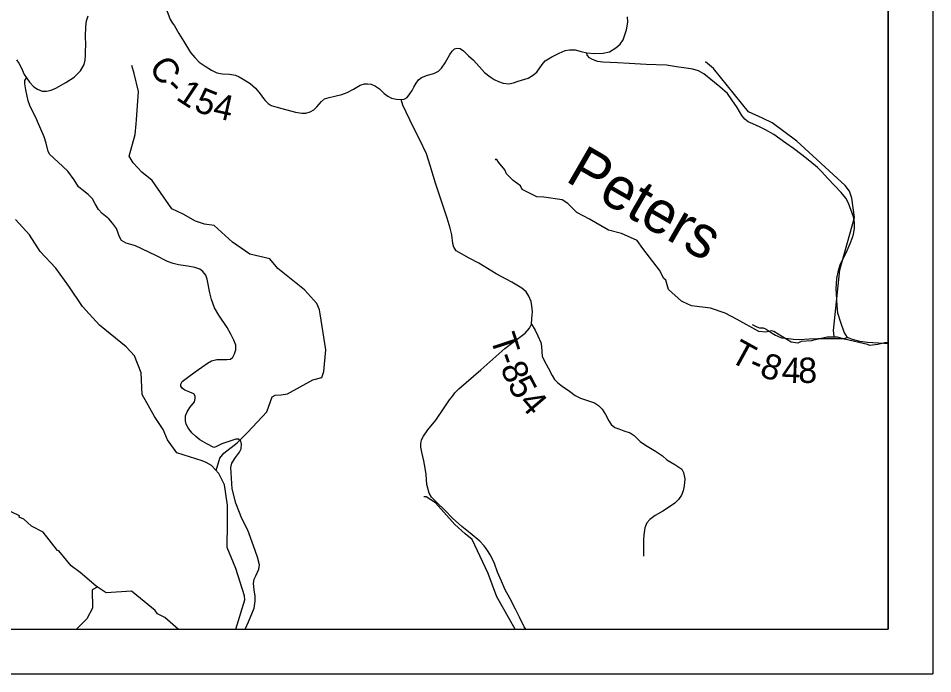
# Model space of a CAD drawing. Extents: x -1.8 to 75.7, y -2 to 25.
# Drawn here: x 48.65 to 50.7, y 15.612 to 17.082 of the extents above; entities that cross this region are included whole.
import ezdxf

# ---------------------------------------------------------------- set-up
doc = ezdxf.new("R2010")
doc.units = 0
for name, color, linetype in [('GM_X_County_Road', 7, 'Continuous'), ('GM_X_County_Road_Text', 7, 'Continuous'), ('GM_X_Minor_River', 7, 'Continuous'), ('GM_X_Minor_River_Text', 7, 'Continuous'), ('GM_X_Township', 7, 'Continuous'), ('GM_X_Township_Road', 7, 'Continuous'), ('GM_X_Township_Road_Text', 7, 'Continuous'), ('SH_Data', 7, 'Continuous')]:
    doc.layers.add(name, color=color, linetype=linetype)

msp = doc.modelspace()

# ---------------------------------------------------------------- linework, layer by layer
at = {"layer": 'GM_X_County_Road'}
for points in [[(48.9834, 17.0995), (48.9906, 17.0793), (48.9956, 17.0713), (49.0001, 17.0657), (49.0103, 17.0484), (49.0213, 17.0302), (49.0361, 17.0057), (49.0458, 16.9942), (49.0558, 16.9842), (49.0692, 16.9747), (49.0833, 16.9656), (49.0952, 16.9599), (49.1076, 16.9576), (49.1234, 16.9569), (49.1371, 16.9547), (49.1455, 16.9508), (49.1545, 16.9456), (49.17, 16.9357), (49.1815, 16.9259), (49.1921, 16.9129), (49.1997, 16.9025), (49.2036, 16.8976), (49.2105, 16.8915), (49.2172, 16.8869), (49.2276, 16.8835), (49.2406, 16.88), (49.2718, 16.8718), (49.2859, 16.8696), (49.2944, 16.8698), (49.3045, 16.8724), (49.3126, 16.8767), (49.3195, 16.8835), (49.3297, 16.8956), (49.3364, 16.9017), (49.3472, 16.9049), (49.3594, 16.9073), (49.3756, 16.9116), (49.3877, 16.9162), (49.4012, 16.9235), (49.4164, 16.932), (49.4259, 16.935), (49.4333, 16.9352), (49.4413, 16.9342), (49.4506, 16.93), (49.4595, 16.924), (49.4705, 16.9138), (49.4785, 16.9073), (49.487, 16.903), (49.498, 16.9006), (49.5083, 16.8999)], [(48.6458, 16.9892), (48.6515, 16.9814), (48.6569, 16.9706), (48.663, 16.9565), (48.6686, 16.9485), (48.6751, 16.9391), (48.6848, 16.9285), (48.6933, 16.9231), (48.7037, 16.9192), (48.7132, 16.919), (48.7234, 16.9212), (48.7338, 16.9259), (48.7563, 16.9381), (48.7756, 16.9504), (48.7893, 16.9647), (48.7974, 16.9788), (48.7997, 16.9885), (48.801, 16.9985), (48.8009, 17.0072), (48.8016, 17.0235), (48.8008, 17.0416), (48.8012, 17.0635), (48.8029, 17.077), (48.8064, 17.0878)], [(49.5083, 16.8999), (49.5155, 16.901), (49.5216, 16.9047), (49.528, 16.9131), (49.533, 16.9206), (49.5369, 16.9275), (49.5421, 16.9368), (49.5476, 16.9444), (49.5542, 16.9496), (49.5677, 16.9546), (49.5818, 16.9587), (49.5921, 16.9637), (49.5991, 16.9703), (49.6073, 16.9824), (49.6172, 17.0009), (49.6224, 17.0089), (49.6283, 17.0141), (49.634, 17.0155), (49.6406, 17.0148), (49.6484, 17.0093), (49.6593, 16.9982), (49.6703, 16.9884), (49.6764, 16.982), (49.684, 16.9733), (49.6954, 16.9608), (49.7077, 16.951), (49.7166, 16.9453), (49.7266, 16.9403), (49.7369, 16.9368), (49.7501, 16.9355), (49.7601, 16.9373), (49.7711, 16.9412), (49.793, 16.9481), (49.8032, 16.9541), (49.8123, 16.9612), (49.8242, 16.979), (49.8312, 16.987), (49.8461, 16.9957), (49.8625, 17.0041), (49.8764, 17.0098), (49.8862, 17.0114), (49.8983, 17.0116), (49.9122, 17.0082), (49.9247, 17.0051), (49.942, 17.0032), (49.9611, 17.0041), (49.9756, 17.0074), (49.9894, 17.0159), (49.9991, 17.024), (50.0061, 17.0341), (50.0135, 17.0561), (50.0164, 17.0734), (50.0155, 17.0857)]]:
    msp.add_lwpolyline(points, dxfattribs=at)
at = {"layer": 'GM_X_Minor_River'}
for points in [[(49.0935, 16.0677), (49.1021, 16.0953), (49.1107, 16.1072), (49.1409, 16.1297), (49.1647, 16.154), (49.2073, 16.1997), (49.2193, 16.2335), (49.2262, 16.2371), (49.2394, 16.2378), (49.2535, 16.24), (49.31, 16.2716), (49.3306, 16.2763), (49.3348, 16.2898), (49.3393, 16.3387), (49.3266, 16.4192), (49.325, 16.4284), (49.319, 16.4426), (49.2916, 16.4731), (49.2318, 16.5209), (49.2139, 16.5424), (49.1689, 16.5533), (49.13, 16.5804), (49.0892, 16.6178), (49.0673, 16.6204), (49.0471, 16.6271), (49.02, 16.6431), (48.9939, 16.6546), (48.9505, 16.7186), (48.9273, 16.7372), (48.9075, 16.7584), (48.8985, 16.7727), (48.9117, 16.8216), (48.9143, 16.8459), (48.9153, 16.8549), (48.9195, 16.9182), (48.9098, 16.9584), (48.9043, 16.9768)], [(50.4794, 16.3684), (50.4775, 16.3822), (50.4923, 16.5182), (50.5247, 16.6358), (50.5185, 16.6788), (50.5137, 16.6944), (50.5039, 16.707), (50.3957, 16.8066), (50.3402, 16.8476), (50.3182, 16.858), (50.2872, 16.8727), (50.2089, 16.9697), (50.1904, 16.9843)], [(50.6002, 16.3545), (50.593, 16.354), (50.5768, 16.3509), (50.559, 16.3486), (50.5541, 16.3509), (50.5023, 16.3625), (50.4868, 16.3671), (50.4634, 16.367), (50.4309, 16.3597), (50.4286, 16.3586), (50.4052, 16.357), (50.398, 16.3539), (50.3829, 16.3558), (50.3439, 16.38), (50.3386, 16.3815), (50.3258, 16.3781), (50.3106, 16.38), (50.2615, 16.4068), (50.235, 16.4208), (50.2017, 16.4322), (50.1594, 16.4374), (50.1397, 16.4465), (50.1367, 16.448), (50.1079, 16.4741), (50.1019, 16.4946), (50.0977, 16.4988), (50.0879, 16.517), (50.05, 16.566), (50.0379, 16.5842), (50.0027, 16.5997), (49.9729, 16.6072), (49.9305, 16.6314), (49.9025, 16.647), (49.8821, 16.6667), (49.8692, 16.675), (49.828, 16.681), (49.8129, 16.6821), (49.8008, 16.6878), (49.7962, 16.69), (49.78, 16.698), (49.7762, 16.7063), (49.7599, 16.7185), (49.7448, 16.7333), (49.741, 16.7424), (49.7266, 16.7598), (49.7228, 16.7659), (49.7202, 16.7651), (49.7213, 16.7678)], [(49.1376, 15.7121), (49.1578, 15.7776), (49.1573, 15.7867), (49.1377, 15.8481), (49.1183, 15.8954), (49.1188, 15.9501), (49.1189, 15.9903), (49.1124, 16.0361), (49.0995, 16.0612), (49.083, 16.0788), (49.0715, 16.0856), (49.0622, 16.0897), (49.0057, 16.1075), (48.9846, 16.137), (48.9751, 16.1601), (48.9552, 16.1888), (48.928, 16.2387), (48.9253, 16.287), (48.9102, 16.3254), (48.8915, 16.345), (48.8318, 16.394), (48.7941, 16.4362), (48.7634, 16.4812), (48.734, 16.5217), (48.6992, 16.5589), (48.675, 16.5965), (48.6436, 16.6309)], [(48.8468, 15.7937), (48.8248, 15.8084), (48.7884, 15.8395), (48.7684, 15.8543), (48.7408, 15.888), (48.7377, 15.8884), (48.7059, 15.9294), (48.6799, 15.943), (48.6621, 15.9589), (48.6519, 15.9634), (48.6526, 15.9661), (48.6182, 15.9824), (48.6008, 16.0017), (48.5944, 16.0028), (48.5713, 16.0347), (48.5539, 16.0487), (48.5417, 16.0418), (48.5506, 16.0468)], [(49.7637, 15.7121), (49.7227, 15.7842), (49.7035, 15.8368), (49.6673, 15.9132), (49.6522, 15.9262), (49.629, 15.9471), (49.5855, 15.9955), (49.5644, 16.0091), (49.5596, 16.009)], [(48.8285, 15.8067), (48.8153, 15.8003), (48.8163, 15.7589), (48.8039, 15.7354), (48.7803, 15.7121)], [(48.9036, 15.797), (48.8468, 15.7937)], [(49.0087, 15.7121), (48.9783, 15.7381), (48.9624, 15.7464), (48.9567, 15.754), (48.9079, 15.7945), (48.9036, 15.797)]]:
    msp.add_lwpolyline(points, dxfattribs=at)
at = {"layer": 'GM_X_Township'}
msp.add_lwpolyline([(47.7632, 15.7121), (50.6002, 15.7121), (50.6002, 18.6397)], dxfattribs=at)
at = {"layer": 'GM_X_Township_Road'}
for points in [[(50.6002, 16.3529), (50.5906, 16.3529), (50.5538, 16.3551), (50.5369, 16.3575), (50.5205, 16.3618), (50.5094, 16.3661), (50.5014, 16.3786), (50.4944, 16.4001), (50.4875, 16.421), (50.4861, 16.4382), (50.485, 16.4516), (50.4837, 16.4753), (50.4851, 16.4985), (50.4888, 16.5164), (50.4925, 16.5292), (50.4962, 16.5373), (50.5059, 16.5565), (50.5153, 16.5769), (50.5201, 16.5909), (50.5225, 16.5983), (50.5251, 16.6107), (50.5251, 16.6242), (50.5223, 16.6372), (50.5116, 16.6677), (50.5055, 16.679), (50.4949, 16.6919), (50.465, 16.7232), (50.4511, 16.7385), (50.4419, 16.7478), (50.4243, 16.7621), (50.4065, 16.7761), (50.3879, 16.7901), (50.3705, 16.8021), (50.3442, 16.8217), (50.325, 16.8325), (50.3135, 16.8384), (50.2971, 16.8456), (50.2865, 16.8504), (50.2791, 16.8558), (50.2721, 16.8643), (50.2615, 16.8822), (50.2499, 16.8994), (50.2397, 16.9133), (50.2227, 16.9285), (50.187, 16.9579), (50.1748, 16.9643), (50.1626, 16.9682), (50.1472, 16.9706), (50.126, 16.9738), (50.1034, 16.9769), (50.0574, 16.9789), (50.0194, 16.981), (49.9934, 16.9826), (49.9603, 16.9836), (49.9484, 16.9856), (49.9357, 16.9908), (49.9307, 16.9939), (49.9253, 16.9993), (49.9247, 17.0051)], [(48.6915, 16.8543), (48.6757, 16.8867), (48.6718, 16.8975), (48.6669, 16.9222), (48.6643, 16.935), (48.6647, 16.943), (48.6686, 16.9485)], [(49.6242, 16.2358), (49.6291, 16.2423), (49.6379, 16.2509), (49.6874, 16.2934), (49.7405, 16.3413), (49.7567, 16.3536), (49.7861, 16.3762), (49.7958, 16.3869), (49.8007, 16.3959), (49.8014, 16.4091), (49.8027, 16.4241), (49.8014, 16.437), (49.7997, 16.447), (49.7949, 16.459), (49.7884, 16.4685), (49.7788, 16.4773), (49.7565, 16.4902), (49.7213, 16.5092), (49.6823, 16.533), (49.661, 16.5446), (49.6439, 16.5538), (49.6319, 16.561), (49.6265, 16.5691), (49.6242, 16.5775), (49.6219, 16.5968), (49.6182, 16.6119), (49.6115, 16.6341), (49.5844, 16.7148), (49.574, 16.7497), (49.5655, 16.7784), (49.5493, 16.8112), (49.5356, 16.8387), (49.5121, 16.8871), (49.5083, 16.8999)], [(49.1593, 15.7121), (49.1596, 15.7132), (49.1665, 15.7282), (49.1791, 15.7591), (49.1813, 15.7745), (49.181, 15.7862), (49.1789, 15.8005), (49.1776, 15.8148), (49.1789, 15.8243), (49.1823, 15.8319), (49.1895, 15.8464), (49.191, 15.8562), (49.1865, 15.8737), (49.1771, 15.8991), (49.165, 15.9342), (49.1511, 15.9606), (49.1381, 15.9949), (49.1295, 16.0269), (49.1264, 16.0746), (49.129, 16.0843), (49.1373, 16.0969), (49.1457, 16.1088), (49.1494, 16.1164), (49.1501, 16.1268), (49.1488, 16.1335), (49.144, 16.1381), (49.1377, 16.1381), (49.1063, 16.1277), (49.1004, 16.1251), (49.0931, 16.1207), (49.0881, 16.1192), (49.0727, 16.1275), (49.0569, 16.137), (49.0482, 16.1441), (49.0393, 16.1528), (49.0307, 16.1634), (49.0265, 16.1721), (49.0252, 16.1792), (49.0246, 16.1903), (49.0285, 16.1996), (49.0348, 16.2094), (49.045, 16.2219), (49.0469, 16.2293), (49.0469, 16.2349), (49.0439, 16.2401), (49.0348, 16.244), (49.0237, 16.2482), (49.0181, 16.2518), (49.0146, 16.2568), (49.0146, 16.2618), (49.0177, 16.2679), (49.0291, 16.2765), (49.0467, 16.2893), (49.0612, 16.2995), (49.0742, 16.3088), (49.0831, 16.314), (49.0948, 16.3166), (49.1054, 16.3173), (49.1175, 16.3166), (49.1256, 16.3177), (49.1308, 16.322), (49.1351, 16.3298), (49.1377, 16.3389), (49.1379, 16.3491), (49.1334, 16.3602), (49.1266, 16.3738), (49.1182, 16.3888), (49.0993, 16.4161), (49.0902, 16.4332), (49.0835, 16.4518), (49.0798, 16.4666), (49.0736, 16.4969), (49.0705, 16.506), (49.0638, 16.5142), (49.0567, 16.5199), (49.0456, 16.5236), (49.03, 16.5264), (49.0092, 16.5294), (48.9969, 16.5322), (48.9845, 16.537), (48.9587, 16.5502), (48.9126, 16.5719), (48.892, 16.5779), (48.8816, 16.5842), (48.8768, 16.5918), (48.8699, 16.6107), (48.8614, 16.623), (48.8528, 16.6323), (48.8382, 16.6445), (48.8296, 16.6531), (48.8226, 16.6659), (48.8164, 16.677), (48.807, 16.6871), (48.7925, 16.698), (48.7847, 16.7043), (48.7754, 16.7196), (48.7611, 16.7396), (48.7397, 16.7595), (48.721, 16.7771), (48.7173, 16.7836), (48.7126, 16.802), (48.7078, 16.8161), (48.6933, 16.8505), (48.6915, 16.8543)], [(49.8007, 16.3959), (49.8085, 16.3825), (49.8148, 16.37), (49.8215, 16.3552), (49.8229, 16.3471), (49.8236, 16.3341), (49.8245, 16.3244), (49.83, 16.3134), (49.8379, 16.2981), (49.8469, 16.2807), (49.8522, 16.2719), (49.8594, 16.2645), (49.8696, 16.2569), (49.8855, 16.246), (49.8985, 16.2365), (49.9107, 16.2305), (49.9288, 16.2241), (49.9422, 16.2199), (49.9512, 16.2141), (49.9591, 16.2058), (49.9667, 16.1933), (49.9741, 16.179), (49.979, 16.1713), (49.9873, 16.1644), (49.9961, 16.1612), (50.0076, 16.1572), (50.0215, 16.1521), (50.0308, 16.1464), (50.0442, 16.1329), (50.0564, 16.1246), (50.0786, 16.1116), (50.0941, 16.101), (50.1038, 16.092), (50.1223, 16.0816), (50.1376, 16.0712), (50.1415, 16.0636), (50.1443, 16.0492), (50.1427, 16.0333), (50.1404, 16.0226), (50.1367, 16.0127), (50.1302, 16.003), (50.1219, 15.9944), (50.1097, 15.9861), (50.0948, 15.9766), (50.0779, 15.9671), (50.0657, 15.9583), (50.0592, 15.9503), (50.0546, 15.9396), (50.0523, 15.9234), (50.0516, 15.9119), (50.0517, 15.8759)], [(50.2956, 16.3956), (50.3056, 16.3903), (50.3121, 16.3882), (50.32, 16.3877), (50.3271, 16.3851), (50.3401, 16.376), (50.3477, 16.3718), (50.3615, 16.3657), (50.3706, 16.3645), (50.3878, 16.3624), (50.4016, 16.3618), (50.423, 16.3633), (50.4427, 16.3639), (50.4703, 16.3642), (50.5006, 16.3639), (50.5094, 16.3661)], [(49.7879, 15.7121), (49.7845, 15.7176), (49.7741, 15.7389), (49.7644, 15.7567), (49.7521, 15.7817), (49.7417, 15.7999), (49.7334, 15.8194), (49.7246, 15.8397), (49.7174, 15.8596), (49.7084, 15.8783), (49.7005, 15.891), (49.6945, 15.8989), (49.685, 15.9091), (49.6628, 15.9271), (49.6441, 15.9424), (49.6235, 15.9611), (49.6062, 15.9787), (49.5886, 15.9965), (49.5766, 16.0083), (49.571, 16.0171), (49.5659, 16.0367), (49.5648, 16.0592), (49.5625, 16.0733), (49.5592, 16.0897), (49.5544, 16.1091), (49.5525, 16.1202), (49.5527, 16.1279), (49.5539, 16.1371), (49.5583, 16.145), (49.568, 16.1595), (49.5858, 16.181), (49.605, 16.2083), (49.6171, 16.2261), (49.6242, 16.2358)]]:
    msp.add_lwpolyline(points, dxfattribs=at)
at = {"layer": 'SH_Data'}
for p, q in [((50.7002, 22.6121), (50.7002, 15.6121)), ((50.6002, 22.5121), (50.6002, 15.7121)), ((50.6002, 22.5121), (50.6002, 15.7121)), ((43.8002, 15.7121), (50.6002, 15.7121)), ((43.8002, 15.7121), (50.6002, 15.7121)), ((43.7002, 15.6121), (50.7002, 15.6121))]:
    msp.add_line(p, q, dxfattribs=at)

# ---------------------------------------------------------------- texts
at = {"layer": 'GM_X_County_Road_Text'}
for s, rotation, p in [('C', 304.4998, (48.9412, 16.9729)), ('-', 316.1355, (48.9758, 16.9248)), ('1', 326.5173, (49.0013, 16.9016)), ('5', 337.7555, (49.0413, 16.8767)), ('4', 347.5203, (49.0838, 16.8603))]:
    msp.add_text(s, height=0.0568, rotation=rotation, dxfattribs=at).set_placement(p)
at = {"layer": 'GM_X_Minor_River_Text'}
msp.add_text('Peters', height=0.0947, rotation=329.9981, dxfattribs=at).set_placement((49.874, 16.7186))
at = {"layer": 'GM_X_Township_Road_Text'}
for s, rotation, p in [('T', 288.1334, (49.7075, 16.3657)), ('T', 331.284, (50.2419, 16.3146)), ('-', 289.1162, (49.721, 16.3243)), ('8', 340.4651, (50.3096, 16.2807)), ('4', 357.7233, (50.3608, 16.2655)), ('8', 0.7219, (50.399, 16.2641)), ('8', 292.8593, (49.7301, 16.2985)), ('-', 336.2262, (50.284, 16.2918)), ('5', 297.6236, (49.7459, 16.2616)), ('4', 310.4716, (49.7699, 16.2191))]:
    msp.add_text(s, height=0.0568, rotation=rotation, dxfattribs=at).set_placement(p)

doc.saveas('drawing.dxf')
